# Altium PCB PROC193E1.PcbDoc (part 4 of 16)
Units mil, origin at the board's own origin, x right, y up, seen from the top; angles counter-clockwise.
Board outline 7700 x 2300 mil, 6 copper layers (Top Layer, GND 1, SIG 1, PWR, GND 2, Bottom Layer), stack 60.98 mil thick; 946 components, 667 nets, 9401 pads, 1730 vias.
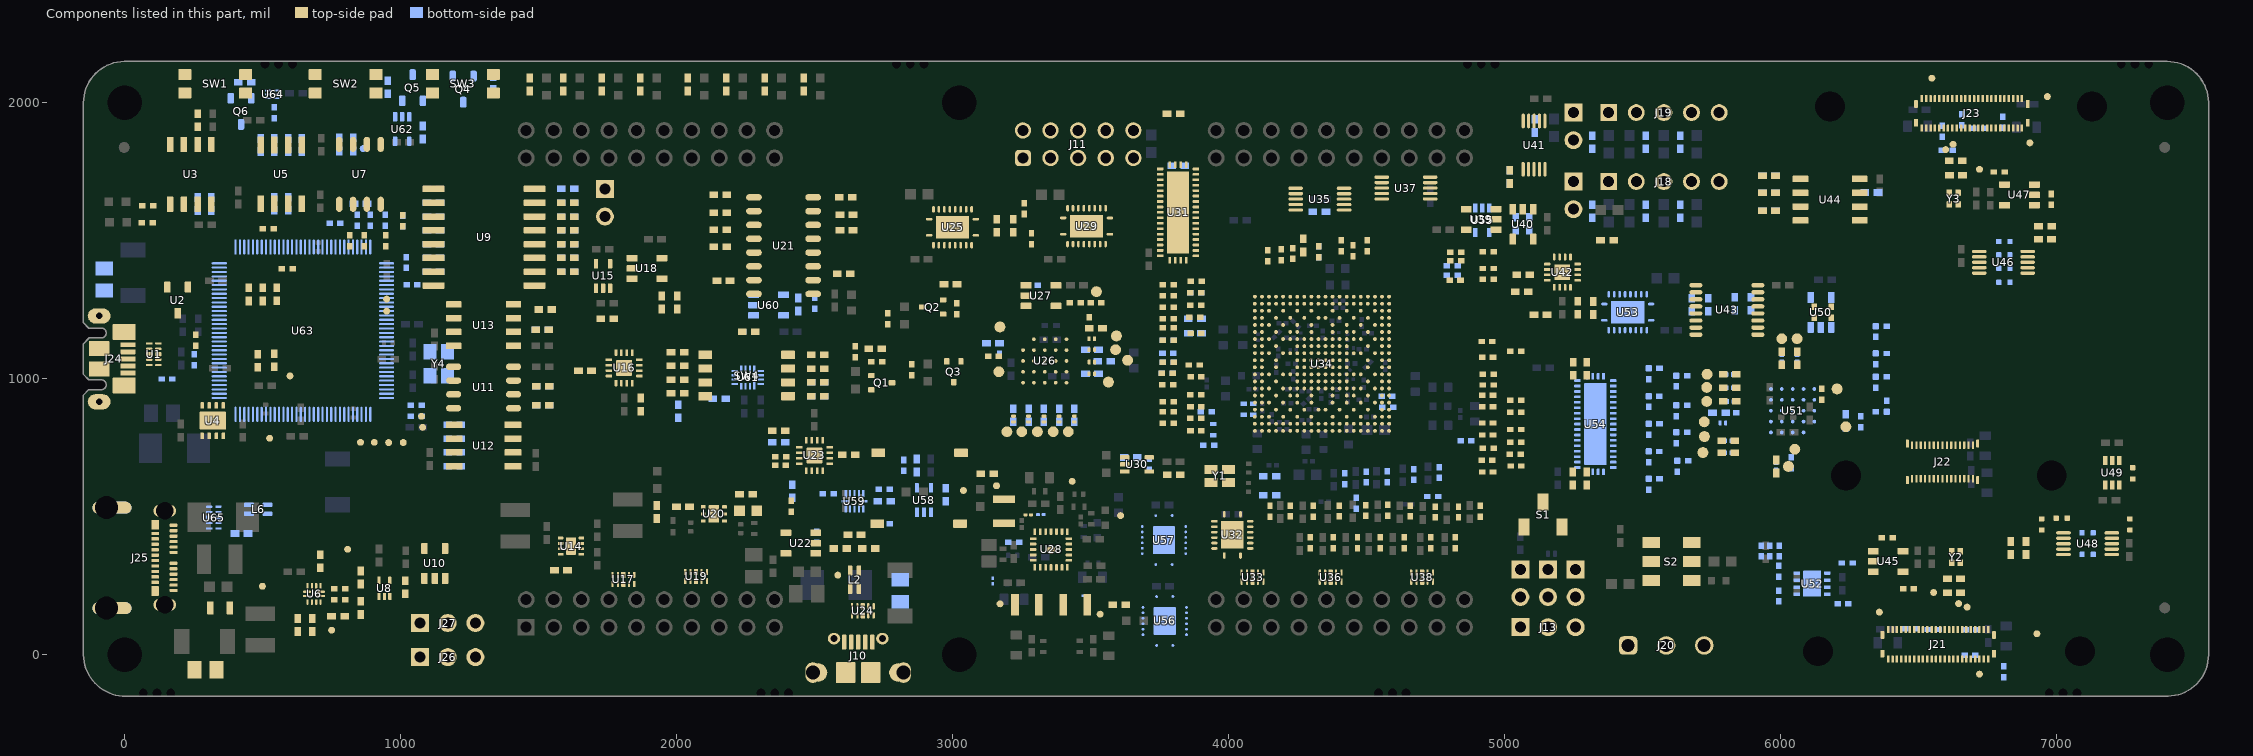
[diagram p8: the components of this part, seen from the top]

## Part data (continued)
J9 J12 J14 J15 J16 J17: library part CMP-0054566-1, "Header, 100mil, 2x1, Gold, TH", Color=Black, Current_A=3A, Manufacturer="Sullins Connector Solutions", Supplier Part Number 1=S1011E-02-ND, Voltage_V=1.8kV
J10: library part CMP-0097752-1, "Conn Micro USB 2.0 Type AB RCP 5 POS 0.65mm Solder RA SMD 5 Terminal 1 Port T/R", Current_A=1A, Digikey Part Number=732-5961-1-ND, Manufacturer="Wurth Electronics", Mouser Part Number=710-629105150921, Operating Temperature Range="-40°C to +85°C", Voltage_V=30V
J11: library part CMP-0080722-2, "Header, 2.54mm, 5x2, Gold, TH", Color=Black, Current_A=3A, Manufacturer="Sullins Connector Solutions", Supplier Part Number 1=S2011EC-05-ND, Voltage_V=1kV
J13 J26 J27: library part CMP-0002334-1, "Header, 100mil, 3x1, Gold, TH", Manufacturer="Sullins Connector Solutions", Supplier Part Number 1=S1011E-03-ND
J18 J19: library part CMP-0054597-1, "Header, 2.54mm, 5x1, Tin, TH", Color=Black, Current_A=3A, Manufacturer="Sullins Connector Solutions", Supplier Part Number 1=S1012E-05-ND, Voltage_V=1.8kV
J20: library part CMP-0075352-1, "Terminal Block, 3.5mm, 3x1, Tin, R/A, TH", Color=Blue, Current_A=10A, Manufacturer="On-Shore Technology", Supplier Part Number 1=ED2636-ND, Voltage_V=125V
J21 J23: library part CMP-0121592-1, "48 Position Connector Plug, Outer Shroud Contacts Surface Mount Gold", Current_A=300mA, Digikey Part Number=H124956CT-ND, Manufacturer=Hirose, Mouser Part Number=798-DF40GB48DP04V58, Operating Temperature Range="-55°C to +85°C", Voltage_V=50V
J22: library part CMP-0121593-1, "30 Position Connector Receptacle, Center Strip Contacts Surface Mount Gold", Current_A=300mA, Digikey Part Number=H124958CT-ND, Manufacturer=Hirose, Mouser Part Number=798-DF40GB1530DS4V58, Operating Temperature Range="-55°C to +85°C", Voltage_V=50V
J24: library part CMP-0055311-1, "Receptacle, USB 2.0, Micro B, 5 Position, R/A, SMT", Color=Black, Current_A=1.8A, Manufacturer=Molex, Supplier Part Number 1=WM11263CT-ND, Voltage_V=30V
J25: library part CMP-0093552-1, "USB-C (USB TYPE-C) USB 3.2 Gen 2 (USB 3.1 Gen 2, Superspeed + (USB 3.1)) Receptacle Connector 24 Position Surface Mount, Right Angle; Through Hole", Digikey Part Number=WM17992CT-ND, Manufacturer=Molex, Mouser Part Number=538-201267-0005, Operating Temperature Range="-40°C to +105°C", Voltage_V=30V
L1: library part CMP-0098084-1, "Chip Ferrite Bead, 0805, 30Ω @ 100MHz, 0.014Ω, , 4A", Impedance At Frequency="30Ω @ 100MHz", Manufacturer=Murata, Operating Temperature Range="-55°C to +125°C", Test Frequency=100MHz
L2 L6: library part CMP-0076826-3, "Coupled inductor, 0.28 A, 0.41 ohm, SMD", Manufacturer=MuRata, Supplier Part Number 1=490-5134-1-ND
L3: library part CMP-0062880-1, "Inductor, Film, 1.5 uH, 3.1 A, 0.06 ohm, AEC-Q200 Grade 0, SMD", Manufacturer=TDK, Value1="0.06 ohm", Value2=3.1A, ValueDisplayed=1.5uH
L4 L5: library part CMP-0062879-1, "Inductor, Film, 1 uH, 3.7 A, 0.042 ohm, AEC-Q200 Grade 0, SMD", Manufacturer=TDK, Value1="0.042 ohm", Value2=3.7A, ValueDisplayed=1uH
LBL1: library part CMP-0003625-1, "Thermal Transfer Printable Labels, 0.650\" W x 0.200\" H - 10,000 per roll", Manufacturer=Brady, Supplier Part Number 1=97C5133
Logo1: library part CMP-0074844-1
Logo2: library part CMP-0074838-1, "Texas Instrument Corporate Signature"
Logo3: library part CMP-0074847-1, "FCC_disclaimer"
Logo4: library part CMP-0074769-1
Q1 Q3: library part CMP-0000010-3, "MOSFET, P-CH, -20 V, -0.39 A, SOT-323", Alternate Manufacturer=None, Manufacturer="Infineon Technologies", Value1=1
Q2: library part CMP-0000948-2, "MOSFET, N-CH, 100 V, 0.17 A, SOT-323", Alternate Manufacturer=None, Manufacturer="Diodes Inc.", Supplier Part Number 1=BSS123W-FDICT-ND, Value1=1
Q4 Q5 Q6: library part CMP-0078819-2, "MOSFET, P-CH, -12 V, -4.3 A, SOT-23", Alternate Manufacturer=None, Manufacturer="Infineon Technologies", Value1="0.05 ohm", Value2="10 nC"
R1 R2 R79 R83 R84: library part CMP-0078194-1, "RES, 360, 5%, 0.1 W, AEC-Q200 Grade 0, 0402", Manufacturer=Panasonic, Power_W=100mW, Supplier Part Number 1=P360JCT-ND, TempCo="200 ppm/C", Tolerance_%=5%, Value2=0.1W, Value_Code=360R, ValueDisplayed=360
R3 R352 R416: library part CMP-0020616-3, "RES, 0, 5%, 0.125 W, AEC-Q200 Grade 0, 0805", Manufacturer=Panasonic, Power_W=125mW, Supplier Part Number 1=P0.0ACT-ND, TempCo="600 ppm/C", Tolerance_%=5%, Value2=0.125W, Value_Code=0000, ValueDisplayed=0
R4 R6 R8 R11 R27 R28 R29 R138: library part CMP-0026299-2, "RES, 33.2, 1%, 0.063 W, AEC-Q200 Grade 0, 0402", Manufacturer=Vishay-Dale, Power_W=63mW, Supplier Part Number 1=541-33.2LCT-ND, TempCo="100 ppm/C", Tolerance_%=1%, Value2=0.063W, Value_Code=33R2, ValueDisplayed=33.2
R5 R9 R12 R19 R22 R23 R24 R394 R396 R398 R399: library part CMP-0026071-3, "RES, 1.00 k, 1%, 0.063 W, AEC-Q200 Grade 0, 0402", Manufacturer=Vishay-Dale, Power_W=63mW, Supplier Part Number 1=541-1.00KLCT-ND, TempCo="100 ppm/C", Tolerance_%=1%, Value2=0.063W, Value_Code=1k00, ValueDisplayed=1.00k
R7: library part CMP-0026437-2, "RES, 51.1 k, 1%, 0.063 W, AEC-Q200 Grade 0, 0402", Manufacturer=Vishay-Dale, Power_W=63mW, Supplier Part Number 1=541-51.1KLCT-ND, TempCo="100 ppm/C", Tolerance_%=1%, Value2=0.063W, Value_Code=51k1, ValueDisplayed=51.1k
R10: library part CMP-0078244-2, "RES, 30.0 k, 1%, 0.063 W, AEC-Q200 Grade 0, 0402", Manufacturer=Vishay-Dale, Power_W=63mW, Supplier Part Number 1=541-30.0KLCT-ND, TempCo="100 ppm/C", Tolerance_%=1%, Value2=0.063W, Value_Code=30k0, ValueDisplayed=30.0k
R13 R57 R73 R183 R185 R205 R337 R379 R382 R403 R404 R406 R409: library part CMP-0026938-5, "RES, 4.7 k, 5%, 0.063 W, AEC-Q200 Grade 0, 0402", Manufacturer=Vishay-Dale, Power_W=63mW, Supplier Part Number 1=541-4.7KJCT-ND, TempCo="200 ppm/C", Tolerance_%=5%, Value2=0.063W, Value_Code=4k70, ValueDisplayed=4.7k
R14: library part CMP-0026603-2, "RES, 909 k, 1%, 0.063 W, AEC-Q200 Grade 0, 0402", Manufacturer=Vishay-Dale, Power_W=63mW, Supplier Part Number 1=541-909KLCT-ND, TempCo="100 ppm/C", Tolerance_%=1%, Value2=0.063W, Value_Code=909k
R15 R68 R69 R70 R71 R74 R85 R101 R195 R374: library part CMP-0078193-1, "RES, 1.0 k, 5%, 0.1 W, AEC-Q200 Grade 0, 0402", Manufacturer=Panasonic, Power_W=100mW, Supplier Part Number 1=P1.0KJCT-ND, TempCo="200 ppm/C", Tolerance_%=5%, Value2=0.1W, Value_Code=1k00, ValueDisplayed=1.0k
R16: library part CMP-0026873-2, "RES, 200 k, 5%, 0.063 W, AEC-Q200 Grade 0, 0402", Manufacturer=Vishay-Dale, Power_W=63mW, Supplier Part Number 1=541-200KJCT-ND, TempCo="200 ppm/C", Tolerance_%=5%, Value2=0.063W, Value_Code=200k
R17 R18 R32 R33 R34 R35 R36 R37 R45 R64 R65 R72 R78 R80 R93 R96 R108 R109 R110 R111 R112 R113 R114 R115 R116 R117 R118 R119 R122 R123 R124 R125 R126 R127 R128 R129 R130 R131 R132 R133 R134 R136 R139 R140 R141 R142 R143 R144 R145 R146 R147 R148 R149 R150 R151 R152 R153 R154 R155 R156 R157 R158 R159 R160 R161 R162 R163 R164 R165 R166 R168 R169 R170 R171 R172 R173 R174 R176 R177 R178 R179 R181 R182 R211 R212 R213 R214 R241 R242 R243 R244 R245 R247 R248 R249 R251 R252 R265 R276 R277 R278 R279 R282 R283 R284 R285 R286 R287 R288 R289 R290 R291 R292 R293 R294 R295 R304 R305 R306 R307 R308 R309 R312 R313 R314 R315 R317 R320 R321 R323 R324 R325 R326 R327 R329 R330 R331 R332 R365 R367 R380 R381 R391 R400 R405 R407 R408 R412 R413: library part CMP-0026992-3, "RES, 0, 5%, 0.1 W, AEC-Q200 Grade 0, 0402", Manufacturer=Panasonic, Power_W=100mW, Supplier Part Number 1=P0.0JCT-ND, TempCo="600 ppm/C", Tolerance_%=5%, Value2=0.1W, Value_Code=0000, ValueDisplayed=0
R20 R21 R25 R30 R31 R39 R43 R46 R47 R48 R49 R50 R51 R53 R54 R55 R56 R61 R63 R75 R76 R77 R81 R90 R91 R120 R175 R184 R186 R187 R188 R189 R190 R191 R200 R201 R202 R216 R217 R218 R219 R246 R258 R259 R260 R266 R267 R274 R275 R301 R302 R303 R316 R318 R328 R358 R359 R362 R363 R364 R366 R368 R369 R370 R371 R372 R373 R375 R376 R377 R378 R383 R384 R385 R386 R387 R388 R389 R395 R397 R401 R410 R411: library part CMP-0026658-1, "RES, 10.0 k, 1%, 0.1 W, 0402", Manufacturer=Panasonic, Power_W=100mW, Supplier Part Number 1=P10.0KLCT-ND, TempCo="100 ppm/C", Tolerance_%=1%, Value2=0.1W, Value_Code=10k0, ValueDisplayed=10.0k
R26 R38 R41 R42 R52 R58 R62 R67: library part CMP-0026680-1, "RES, 220, 1%, 0.1 W, AEC-Q200 Grade 0, 0402", Manufacturer=Panasonic, Power_W=100mW, Supplier Part Number 1=P220LCT-ND, TempCo="100 ppm/C", Tolerance_%=1%, Value2=0.1W, Value_Code=220R, ValueDisplayed=220
R40: library part CMP-0026703-1, "RES, 49.9, 1%, 0.1 W, AEC-Q200 Grade 0, 0402", Manufacturer=Panasonic, Power_W=100mW, Supplier Part Number 1=P49.9LCT-ND, TempCo="100 ppm/C", Tolerance_%=1%, Value2=0.1W, Value_Code=49R9, ValueDisplayed=49.9
R44: library part CMP-0026704-1, "RES, 510, 1%, 0.1 W, 0402", Manufacturer=Panasonic, Power_W=100mW, Supplier Part Number 1=P510LCT-ND, TempCo="100 ppm/C", Tolerance_%=1%, Value2=0.1W, Value_Code=510R, ValueDisplayed=510
R59: library part CMP-0023078-5, "RES, 3.16 k, 1%, 0.1 W, 0603", Manufacturer=Yageo, Power_W=100mW, Supplier Part Number 1=311-3.16KHRCT-ND, TempCo="100 ppm/C", Tolerance_%=1%, Value2=0.1W, Value_Code=3k16, ValueDisplayed=3.16k
R60: library part CMP-0026088-3, "RES, 1.50 k, 1%, 0.063 W, AEC-Q200 Grade 0, 0402", Manufacturer=Vishay-Dale, Power_W=63mW, Supplier Part Number 1=541-1.50KLCT-ND, TempCo="100 ppm/C", Tolerance_%=1%, Value2=0.063W, Value_Code=1k50, ValueDisplayed=1.50k
R66 R89 R99 R102 R199 R206 R207 R208 R209 R210 R215 R221 R231 R232 R233 R234 R235 R236 R237 R238 R239 R240 R250 R255 R257 R264 R322 R333 R340 R344 R346 R348 R353 R355 R356 R357 R360 R361 R392: library part CMP-0025958-3, "RES, 10.0 k, 1%, 0.063 W, AEC-Q200 Grade 0, 0402", Manufacturer=Vishay-Dale, Power_W=63mW, Supplier Part Number 1=541-10.0KLCT-ND, TempCo="100 ppm/C", Tolerance_%=1%, Value2=0.063W, Value_Code=10k0, ValueDisplayed=10.0k
R82 R86: library part CMP-0078212-1, "RES, 510, 5%, 0.1 W, AEC-Q200 Grade 0, 0402", Manufacturer=Panasonic, Power_W=100mW, Supplier Part Number 1=P510JCT-ND, TempCo="200 ppm/C", Tolerance_%=5%, Value2=0.1W, Value_Code=510R, ValueDisplayed=510
R87 R107 R334 R350: library part CMP-0025998-3, "RES, 130, 1%, 0.063 W, AEC-Q200 Grade 0, 0402", Manufacturer=Vishay-Dale, Power_W=63mW, Supplier Part Number 1=541-130LCT-ND, TempCo="100 ppm/C", Tolerance_%=1%, Value2=0.063W, Value_Code=130R, ValueDisplayed=130
R88 R253: library part CMP-0026659-2, "RES, 100 k, 1%, 0.1 W, 0402", Manufacturer=Panasonic, Power_W=100mW, TempCo="100 ppm/C", Tolerance_%=1%, Value2=0.1W, Value_Code=100k
R92 R95 R97 R98 R100 R103 R104 R105 R106 R254 R256 R263 R268 R269 R270 R271 R272 R273: library part CMP-0087090-2, "RES Thick Film SMD 22Ω 1% 1/20W 0201 200ppm/°C", Manufacturer=Vishay, Power_W=50mW, TempCo=200ppm/°C, Tolerance_%=1%
R94 R338 R343 R349: library part CMP-0086442-2, "RES SMD 0 OHM JUMPER 1/20W 0201", Manufacturer=Yageo, Power_W=50mW, TempCo=200ppm/°C, Tolerance_%=5%
R121: library part CMP-0025961-3, "RES, 10.7 k, 1%, 0.063 W, AEC-Q200 Grade 0, 0402", Manufacturer=Vishay-Dale, Power_W=63mW, Supplier Part Number 1=541-10.7KLCT-ND, TempCo="100 ppm/C", Tolerance_%=1%, Value2=0.063W, Value_Code=10k7, ValueDisplayed=10.7k
R135 R137 R167 R180 R310 R311: library part CMP-0026696-1, "RES, 33.0, 1%, 0.1 W, 0402", Manufacturer=Panasonic, Power_W=100mW, Supplier Part Number 1=P33.0LCT-ND, TempCo="100 ppm/C", Tolerance_%=1%, Value2=0.1W, Value_Code=33R0, ValueDisplayed=33.0
R192 R193 R194 R196 R197 R198 R203 R204 R280 R281 R296 R297 R298 R299 R300 R335 R336 R339 R341 R342 R345 R347: library part CMP-0026702-1, "RES, 49.9 k, 1%, 0.1 W, AEC-Q200 Grade 0, 0402", Manufacturer=Panasonic, Power_W=100mW, Supplier Part Number 1=P49.9KLCT-ND, TempCo="100 ppm/C", Tolerance_%=1%, Value2=0.1W, Value_Code=49k9, ValueDisplayed=49.9k
R220 R222 R223 R224 R225 R226 R227 R228 R229 R230: library part CMP-0042990-1, "Res Thick Film 0402 1.5K Ohm 5% 1/10W ±200ppm/°C Molded SMD Punched Carrier T/R", Digikey Part Number=P1.5KJCT-ND, Manufacturer=Panasonic, Mouser Part Number=667-ERJ-2GEJ152X, Octopart Part Number=cecc048b4d5c110b, Operating Temperature Range="-55°C to +155°C", Power_W=100mW, TempCo=200ppm/°C, Tolerance_%=5%, Voltage=50V
R261 R262: library part CMP-0026491-2, "RES, 61.9, 1%, 0.063 W, AEC-Q200 Grade 0, 0402", Manufacturer=Vishay-Dale, Power_W=63mW, Supplier Part Number 1=541-61.9LCT-ND, TempCo="100 ppm/C", Tolerance_%=1%, Value2=0.063W, Value_Code=61R9, ValueDisplayed=61.9
R319: library part CMP-0026240-2, "RES, 2.67 k, 1%, 0.063 W, AEC-Q200 Grade 0, 0402", Manufacturer=Vishay-Dale, Power_W=63mW, Supplier Part Number 1=541-2.67KLCT-ND, TempCo="100 ppm/C", Tolerance_%=1%, Value2=0.063W, Value_Code=2k67, ValueDisplayed=2.67k
R351: library part CMP-0026464-2, "RES, 5.23 k, 1%, 0.063 W, AEC-Q200 Grade 0, 0402", Manufacturer=Vishay-Dale, Power_W=63mW, Supplier Part Number 1=541-5.23KLCT-ND, TempCo="100 ppm/C", Tolerance_%=1%, Value2=0.063W, Value_Code=5k23, ValueDisplayed=5.23k
R354: library part CMP-0026041-3, "RES, 16.5 k, 1%, 0.063 W, AEC-Q200 Grade 0, 0402", Manufacturer=Vishay-Dale, Power_W=63mW, Supplier Part Number 1=541-16.5KLCT-ND, TempCo="100 ppm/C", Tolerance_%=1%, Value2=0.063W, Value_Code=16k5, ValueDisplayed=16.5k
R390: library part CMP-0026993-2, "RES, 100, 5%, 0.1 W, AEC-Q200 Grade 0, 0402", Manufacturer=Panasonic, Power_W=100mW, Supplier Part Number 1=P100JCT-ND, TempCo="200 ppm/C", Tolerance_%=5%, Value2=0.1W, Value_Code=100R, ValueDisplayed=100
R393: library part CMP-0026404-2, "RES, 49.9, 1%, 0.063 W, AEC-Q200 Grade 0, 0402", Manufacturer=Vishay-Dale, Power_W=63mW, Supplier Part Number 1=541-49.9LCT-ND, TempCo="100 ppm/C", Tolerance_%=1%, Value2=0.063W, Value_Code=49R9, ValueDisplayed=49.9
R402: library part CMP-0026413-2, "RES, 4.87 k, 1%, 0.063 W, AEC-Q200 Grade 0, 0402", Manufacturer=Vishay-Dale, Power_W=63mW, Supplier Part Number 1=541-4.87KLCT-ND, TempCo="100 ppm/C", Tolerance_%=1%, Value2=0.063W, Value_Code=4k87, ValueDisplayed=4.87k
R414 R415: library part CMP-0078210-2, "RES, 330 k, 1%, 0.063 W, AEC-Q200 Grade 0, 0402", Manufacturer=Vishay-Dale, Power_W=63mW, Supplier Part Number 1=541-330KLCT-ND, TempCo="100 ppm/C", Tolerance_%=1%, Value2=0.063W, Value_Code=330k
S1: library part CMP-0002139-2, "Switch, Slide, SPDT  100mA, SMT", CurrentRating_mA=100A, Manufacturer="Copal Electronics", Supplier Part Number 1=CAS120JCT-ND
S2: library part CMP-0002233-1, "Switch, Dual SPDT,  2 Pos, 0.1A, 6VDC, SMD", CurrentRating_mA=100A, Manufacturer="Copal Electronics", Supplier Part Number 1=CASD20JCT-ND
SH-J1 SH-J2 SH-J3 SH-J4 SH-J5 SH-J6 SH-J7 SH-J8: library part CMP-0003761-2, "Shunt, 2.54mm, Gold, Black", Manufacturer="Wurth Elektronik", Supplier Part Number 1=732-2678-ND
SW1 SW2 SW3: library part CMP-0093456-1, "Tactile Switch SPST-NO Side Actuated Surface Mount, Right Angle", Coil Resistance_ohm=100mΩ, Contact Current Rating=50mA, Digikey Part Number=732-7057-1-ND, Manufacturer="Wurth Electronics", Mouser Part Number=710-434351045816, Operating Force=160gf, Operating Temperature Range="-40°C to +85°C"
SW4: library part CMP-0093176-1, "Dip Switch SPST 4 Position Surface Mount Slide (Standard) Actuator 25mA 24VDC", Coil Resistance_ohm=100mΩ, Contact Current Rating=25mA, Digikey Part Number=732-3854-1-ND, Manufacturer=Wurth, Mouser Part Number=710-416131160804, Operating Temperature Range="-40°C to +85°C"
SW5 SW6: library part CMP-0094653-1, "Dip Switch SPST 1 Position Surface Mount Slide (Standard) Actuator 25mA 24VDC", Coil Resistance_ohm=100mΩ, Contact Current Rating=25mA, Digikey Part Number=732-3851-1-ND, Manufacturer="Wurth Electronics", Mouser Part Number=710-416131160801, Operating Temperature Range="-40°C to +85°C"
TP1 TP2 TP3 TP4 TP5 TP6 TP7 TP8 TP9 TP10 TP11 TP12 TP13 TP14 TP15 TP16 TP19 TP25 TP27 TP31 TP45 TP46 TP47 TP48 TP49 TP50 TP51 TP52 TP53 TP54 TP55 TP56 TP57: library part CMP-0078143-3, "TEST POINT.  No entry in BOM.", Manufacturer=N/A
TP17 TP18 TP20 TP21 TP22 TP23 TP24 TP26 TP28 TP29 TP30 TP32 TP33 TP34 TP35 TP36 TP37 TP38 TP39 TP40 TP41 TP42 TP43 TP44: library part CMP-0003825-1, "1mm Test Point, SMT", Manufacturer=Any
U1 U17 U19 U24 U33 U36 U38 U65: library part CMP-0073612-3, "4-Channel ESD Protection Diode for USB Type-C and HDMI 2.0, DQA0010A (USON-10)", Alternate Manufacturer="Texas Instruments"
U2: library part CMP-0033001-1, "Precision Micropower Shunt Voltage Reference, 0.5% accuracy, 2.5 V, 15 ppm / degC, 15 mA, -40 to 125 degC, 3-pin SOT-23 (DBZ), Green (RoHS & no Sb/Br)", Manufacturer="Texas Instruments", Rating=Catalog, Temp Coeff(Max)(ppm/ degree C)=100, Temp Coeff(Typ)(ppm/ degree C)=15
U3 U13: library part CMP-0076059-2, "High Speed, Robust EMC Dual-Channel Digital Isolator, D0008B (SOIC-8)", Alternate Manufacturer="Texas Instruments", Alternate PartNumber=ISO7721D, Operating Temperature Range="-55 to 125 C", Rating=Catalog
U4: library part CMP-0036402-3, "Single Output High PSRR LDO, 1 A, Adjustable 1.2 to 5.5 V Output, 2.7 to 5.5 V Input, 8-pin SON (DRB), -40 to 125 degC, Green (RoHS & no Sb/Br)", Manufacturer="Texas Instruments"
U5 U12: library part CMP-0031336-1, "Hot-swappable, robust-EMC bidirectional I2C isolator with unidirectional clock 8-SOIC -40 to 125", Digikey Part Number=296-ISO1641BDRCT-ND, Manufacturer="Texas Instruments", Max Supply Voltage=5.5V, Min Supply Voltage=2.25V, Mouser Part Number=595-ISO1641BDR, Operating Temperature Range="-40°C to +125°C"
U6: library part CMP-0073635-2, "USB Type-C Configuration Channel Logic and Port Control, RWB0012A (X2QFN-12)", Alternate Manufacturer="Texas Instruments", Operating Temperature Range="-40 to 85 C", Rating=Catalog
U7 U11: library part CMP-0029369-1, "25 Mbps Dual Channels, 2 / 0, Digital Isolator, 3.3 V / 5 V, -40 to +125 degC, 8-pin SOIC (D), Green (RoHS & no Sb/Br)", Insulation Rating(VRMS)=2500, Manufacturer="Texas Instruments", Rating=Catalog, Supply Voltage(s)(V)="3.3, 5"
U8: library part CMP-0051530-2, "Single 2-Input Positive-NOR Gate, DRL0005A, LARGE T&R", Alternate Manufacturer="Texas Instruments", F @ Nom Voltage(Max)(Mhz)=75, Generic Part Number=SN74AHC1G02, ICC @ Nom Voltage(Max)(mA)=0.01, Operating Temperature Range(C)="-40 to 125,-40 to 85", Rating=Catalog, tpd @ Nom Voltage(Max)(ns)=11.4,7.5, Voltage(Nom)(V)=3.3,5
U9: library part CMP-0096103-1, "General purpose, 50-Mbps, six-channel (6/0) digital isolator 16-SOIC -40 to 125", Digikey Part Number=296-ISO6760DWRCT-ND, Manufacturer="Texas Instruments", Max Supply Voltage=5.5V, Min Supply Voltage=1.71V, Mouser Part Number=595-ISO6760DWR, Operating Temperature Range="-40°C to +125°C"
U10 U18 U39 U45 U47 U60: library part CMP-0051588-2, "Single 2-Input Positive-AND Gate, DBV0005A, LARGE T&R", Alternate Manufacturer="Texas Instruments", F @ Nom Voltage(Max)(Mhz)=150, Generic Part Number=SN74LVC1G08, ICC @ Nom Voltage(Max)(mA)=0.01, Operating Temperature Range(C)="-40 to 125,-40 to 85", Rating=Catalog, tpd @ Nom Voltage(Max)(ns)=4.5,6,4,5, Voltage(Nom)(V)=1.8,2.5,3.3,5
U14: library part CMP-0073678-3, "5.5V, 4A, 16mΩ Automotive Load Switch With Adjustable Rise Time and Optional Quick Output Discharge, DSG0008B (WSON-8)", Alternate Manufacturer="Texas Instruments", Alternate PartNumber=TPS22965TDSGTQ1
U15: library part CMP-0051704-3, "Single Schmitt-Trigger Buffer, DCK0005A, LARGE T&R", F @ Nom Voltage(Max)(Mhz)=150, Generic Part Number=SN74LVC1G17, ICC @ Nom Voltage(Max)(mA)=0.01, Manufacturer="Texas Instruments", Operating Temperature Range(C)="-40 to 125,-40 to 85", Rating=Catalog, tpd @ Nom Voltage(Max)(ns)=11,6.5,5.5,5, Voltage(Nom)(V)=1.8,2.5,3.3,5
U16 U23 U42: library part CMP-0043157-2, "Low-Voltage 8-Bit I2C and SMBus I/O Expander, 1.65 to 5.5 V, -40 to 85 degC, 16-pin QFN (RGT), Green (RoHS & no Sb/Br)", 5V Tolerant I/O=Yes, Manufacturer="Texas Instruments", Max Frequency(kHz)=400
U20: library part CMP-0084398-1, "500-mA LDO, DRV0006A (WSON-6)", Alternate Manufacturer="Texas Instruments", Alternate PartNumber=TLV75801PDRVT, Operating Temperature Range="-40 to 125 C", Rating=Catalog
U21: library part CMP-0044782-1, "8-Bit LED Driver with I2C Interface, D0016A, TUBE", Generic Part Number=TPIC2810, Manufacturer="Texas Instruments", Operating Temperature Range(C)="-40 to 125", Rating=Catalog
U22: library part CMP-0074276-1, "Single, Current-Limited, Power-Distribution Switch, DBV0005A (SOT-23-5)", Alternate Manufacturer="Texas Instruments", Alternate PartNumber=TPS2051BDBVT
U25 U29 U53: library part CMP-0074359-2, "8-Bit Bidirectional Voltage-Level Shifter with Auto Direction Sensing and +/-15-kV ESD Protect, RGY0020A (VQFN-20)", Alternate Manufacturer="Texas Instruments"
U26: library part CMP-0121596-1, "Octal Flash 64Mbit 8M X 8bit SPI 1.8V 6ns 24-Pin TFBGA", Digikey Part Number=706-IS25WX064-JHLE-ND, Frequency_Fixed=200MHz, Manufacturer=ISSI, Max Supply Voltage=2V, Min Supply Voltage=1.7V, Mouser Part Number=870-IS25WX064-JHLE, Nominal Supply Current=15-70mA, Operating Temperature Range="-40°C to +105°C"
U27 U50: library part CMP-0051264-2, "Single 2-Input Positive–AND Gate with Open Drain Output,  DBV0005A (SOT-23-5)", F @ Nom Voltage(Max)(Mhz)=75, Generic Part Number=SN74AHC1G09, ICC @ Nom Voltage(Max)(mA)=0.01, Manufacturer="Texas Instruments", Operating Temperature Range="-55 to 125 C", Rating=Catalog, tpd @ Nom Voltage(Max)(ns)=11,7.5, Voltage(Nom)(V)=3.3,5
U28: library part CMP-0119993-1, "Automotive Camera PMIC", Manufacturer="Texas Instruments", Max Supply Voltage=35V, Min Supply Voltage=4V, Operating Temperature Range="-40°C to +150°C", Output Voltage=3-5.5/0.6-3.4/0.6-3.4/1.8-3.4V, Part Number=TPS65036
U30 U58: library part CMP-0085889-2, "Small-Size Micropower Low-Voltage Comparator, DCK0005A (SOT-SC70-5)", Alternate Manufacturer="Texas Instruments", Alternate PartNumber=TLV7021DCKT, Operating Temperature Range="-40 to 125 C", Rating=Catalog
U31 U54: library part CMP-0093539-2, "IC MUX/DEMUX DDR3 1:2 42WQFN", Digikey Part Number=296-28307-1-ND, Manufacturer="Texas Instruments", Max Supply Voltage=3.6V, Min Supply Voltage=3V, Mouser Part Number=595-TS3DDR3812RUAR, Nominal Supply Current=300uA, On State Resistance=8Ω, Operating Temperature Range="-40°C to +85°C"
U32: library part CMP-0066250-3, "Dual 1-of-4 FET Multiplexer/Demultiplexer 2.5-V/3.3-V Low-Voltage High-Bandwidth Bus Switch, RGY0016A (VQFN-16)", Alternate Manufacturer="Texas Instruments"
U34: library part AM261x_ZFG304_0p97, "AM261x / Package: ZFG304A / Version: 0p97"
U35 U37 U41 U46 U48: library part CMP-0067419-2, "2-Channel, 2:1 Analog Switch with Low On-State Resistance (1ohm) and Powered Off Protection, DGS0010A (VSSOP-10)", Alternate Manufacturer="Texas Instruments", Alternate PartNumber=TS5A23159DGST, Operating Temperature Range="-40 to 85 C", Rating=Catalog
U40: library part CMP-0052045-2, "Single 2-Input Exclusive-OR Gate, DBV0005A (SOT-23-5)", F @ Nom Voltage(Max)(Mhz)=75, Generic Part Number=SN74AHC1G86, ICC @ Nom Voltage(Max)(mA)=0.01, Manufacturer="Texas Instruments", Operating Temperature Range="-40 to 125 C", Rating=Catalog, tpd @ Nom Voltage(Max)(ns)=14.5,8.8, Voltage(Nom)(V)=3.3,5
U43: library part CMP-0076540-1, "4-Bit One-of-2 FET Multiplexer/Demultiplexer 2.5-V/3.3-V Low-Voltage, High-Bandwidth Bus Switch, PW0016A (TSSOP-16)", Alternate Manufacturer="Texas Instruments"
U44: library part CMP-0005327-2, "1024-Kb I2C CMOS Serial EEPROM, SOIC-8", Manufacturer="ON Semiconductor", Supplier Part Number 1=CAT24M01WI-GT3OSTR-ND
U49: library part CMP-0074352-3, "1-Bit Bidirectional Voltage-Level Shifter for Open-Drain and Push-Pull Application, DCK0006A (SOT-SC70-6)", Alternate Manufacturer="Texas Instruments", Alternate PartNumber=TXS0101DCKT, Operating Temperature Range="-40 to 85,-55 to 125 C", Rating=Catalog
U51: library part CMP-0122153-1, "1.8V 64M-BIT [x 1/x 8] Read-While-Write octaflash Memory", Frequency_Fixed=200MHz, Manufacturer=Macronix, Max Supply Voltage=2V, Min Supply Voltage=1.7V, Nominal Supply Current=18-140mA, Operating Temperature Range="-40°C to +125°C"
U52: library part CMP-0079884-2, "Automotive High Speed CAN Transceiver, DRB0008J (VSON-8)", Alternate Manufacturer="Texas Instruments", Alternate PartNumber=TCAN1044VDRBRQ1
U55: library part CMP-0051644-4, "Single Schmitt-Trigger Inverter, DCK0005A (SOT-SC70-5)", Alternate Manufacturer="Texas Instruments", Alternate PartNumber=SN74LVC1G14DCKR, F @ Nom Voltage(Max)(Mhz)=150, Generic Part Number=SN74LVC1G14, ICC @ Nom Voltage(Max)(mA)=0.01, Operating Temperature Range="-40 to 125 C", Rating=Catalog, tpd @ Nom Voltage(Max)(ns)=11,6.5,5.5,5, Voltage(Nom)(V)=1.8,2.5,3.3,5
U56 U57: library part CMP-0094034-1, "Encoders, Decoders, Multiplexers & Demultiplexers 4-Bit One-of-2 FET Mltplxr/Demltplxr", Digikey Part Number=296-16834-1-ND, Manufacturer="Texas Instruments", Max Supply Voltage=3.6V, Min Supply Voltage=2.3V, Mouser Part Number=595-SN74CB3Q3257RGYR, Nominal Supply Current=0.7mA, Operating Temperature Range="-40°C to +85°C"
U59: library part CMP-0033722-2, "USB 2.0 High-Speed (480 Mbps) and Audio Switch, DP3T, 6.5 ohm RON, -40 to 85 degC, 12-Pin UQFN (RUT), Green (RoHS & no Sb/Br)", Manufacturer="Texas Instruments"
U61: library part CMP-0066450-2, "4-Bit Dual-Supply Bus Transceiver with Configurable Voltage-Level Shifting and 3-State Outputs, RSV0016A (UQFN-16)", Alternate Manufacturer="Texas Instruments"
U62: library part CMP-0051392-2, "Single Buffer/Driver With Open-Drain Output, DCK0005A, SMALL T&R", F @ Nom Voltage(Max)(Mhz)=150, Generic Part Number=SN74LVC1G07, ICC @ Nom Voltage(Max)(mA)=0.01, Manufacturer="Texas Instruments", Operating Temperature Range(C)="-40 to 125,-40 to 85", Rating=Catalog, tpd @ Nom Voltage(Max)(ns)=8.6,6,4.7,4, Voltage(Nom)(V)=1.8,2.5,3.3,5
U63: library part CMP-0029856-2, "Tiva C Series Microcontroller, 1024 KB Flash, 256 KB SRAM, 12 Bit, 20 Channels, -40 to 105 degC, 128-Pin TQFP (PDT), Green (RoHS & no Sb/Br), Tray", Manufacturer="Texas Instruments", Temperature Range="-40 to 105 degC"
U64: library part CMP-0051904-4, "Dual Schmitt-Trigger Buffer, DSF0006A, LARGE T&R", F @ Nom Voltage(Max)(Mhz)=150, Generic Part Number=SN74LVC2G17, ICC @ Nom Voltage(Max)(mA)=0.01, Manufacturer="Texas Instruments", Operating Temperature Range(C)="-40 to 125,-40 to 85", Rating=Catalog, tpd @ Nom Voltage(Max)(ns)=9.3,5.7,5.4,4.3, Voltage(Nom)(V)=1.8,2.5,3.3,5
Y1: library part CMP-0084811-1, "Crystal, 25 MHz, 10 ppm, 4 pF, SMD", Frequency Stability="20 ppm", Frequency Tolerance="10 ppm", Frequency_Fixed=25MHz, Load Capacitance="4 pF", Manufacturer="Abracon Corporation", PartNumber=ABM10W-25.0000MHZ-8-K1Z-T3
Y2 Y3: library part CMP-0093099-1, "25 MHz XO (Standard) CMOS Oscillator 3.3V Enable/Disable 4-SMD, No Lead", Digikey Part Number=535-12075-1-ND, Frequency Stability=30ppm, Frequency_Fixed=25MHz, Load Capacitance=15pF, Manufacturer=Abracon, Max Supply Current=4.2mA, Max Supply Voltage=3.63V, Min Supply Voltage=2.97V, Mouser Part Number=815-ASCO-25-EK-T3, Operating Temperature Range="-20°C to +70°C"
Y4: library part CMP-0004635-3, "Crystal, 16 MHz, 8pF, SMD", Frequency_Fixed=16MHz, Frequency Stability=+/-30ppm, Manufacturer=NDK, Supplier Part Number 1=644-1157-1-ND
ZZ1: library part CMP-0077238-1
ZZ2: library part CMP-0077237-1
ZZ3: library part CMP-0077236-1
ZZ4: library part CMP-0003616-3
